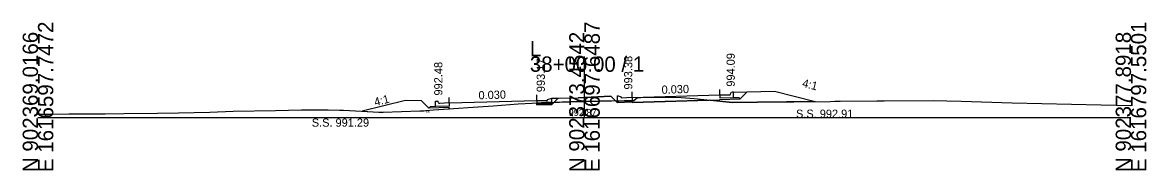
# Model space of a CAD drawing. Extents: x 1009 to 7438, y -1586 to 7964.
# Drawn here: x 3032.1 to 3237.7, y 5914 to 5941 of the extents above; entities that cross this region are included whole.
import ezdxf

# ---------------------------------------------------------------- set-up
doc = ezdxf.new("R2010")
doc.units = 0
for name, color, linetype in [('Exist Cross Section Cell', 7, 'Continuous'), ('Exist XS Center Line Elevation Label', 7, 'Continuous'), ('Exist XS Ground Line', 7, 'Continuous'), ('Prop XS Dump Level', 7, 'Continuous'), ('Prop XS Earthwork Shape', 7, 'Continuous'), ('Prop XS EOT Tick Mark', 7, 'Continuous'), ('Prop XS Finish Grade', 7, 'Continuous'), ('Prop XS Finish Grade CurbGutter', 7, 'Continuous'), ('Prop XS Finish Grade Earthwork', 7, 'Continuous'), ('Prop XS Finish Grade Pavement', 7, 'Continuous'), ('Prop XS Hydro Elevations', 7, 'Continuous'), ('Prop XS Pvmt Edge Slope', 7, 'Continuous'), ('Prop XS SE Text', 7, 'Continuous'), ('Prop XS Side Slope Text', 7, 'Continuous'), ('Prop XS SS Elevation Text', 7, 'Continuous'), ('Prop XS Subgrade CurbGutter', 7, 'Continuous'), ('Prop XS Subgrade Earthwork', 7, 'Continuous')]:
    doc.layers.add(name, color=color, linetype=linetype)

msp = doc.modelspace()

# ---------------------------------------------------------------- linework, layer by layer
at = {"layer": 'Exist Cross Section Cell'}
for p, q in [((3134.89, 5923.73), (3134.89, 5934.84)), ((3034.89, 5923.73), (3134.89, 5923.73)), ((3134.89, 5923.73), (3234.89, 5923.73))]:
    msp.add_line(p, q, dxfattribs=at)
at = {"layer": 'Exist XS Ground Line'}
for p, q in [((3107.24, 5925.08), (3118.2, 5925.81)), ((3118.2, 5925.81), (3122.77, 5926.19)), ((3122.77, 5926.19), (3127.86, 5926.41)), ((3127.86, 5926.41), (3128.42, 5926.43)), ((3128.42, 5926.43), (3132.18, 5926.53)), ((3132.18, 5926.53), (3134.89, 5926.6)), ((3134.89, 5926.6), (3142.32, 5926.79)), ((3142.32, 5926.79), (3143.94, 5926.8)), ((3143.94, 5926.8), (3144.62, 5927.33)), ((3144.62, 5927.33), (3145.2, 5927.34)), ((3145.2, 5927.34), (3149.54, 5927.43)), ((3149.54, 5927.43), (3150.62, 5927.41)), ((3150.62, 5927.41), (3152.55, 5927.35)), ((3152.55, 5927.35), (3154.93, 5927.15)), ((3154.93, 5927.15), (3161.98, 5926.45)), ((3161.98, 5926.45), (3166.57, 5926.5)), ((3166.57, 5926.5), (3179.84, 5926.64)), ((3179.84, 5926.64), (3180.7, 5926.66)), ((3180.7, 5926.66), (3181.66, 5926.67)), ((3181.66, 5926.67), (3188.36, 5926.72)), ((3188.36, 5926.72), (3189.7, 5926.73)), ((3189.7, 5926.73), (3198.69, 5926.8)), ((3198.69, 5926.8), (3201.22, 5926.73)), ((3201.22, 5926.73), (3203.8, 5926.69)), ((3203.8, 5926.69), (3213.15, 5926.35)), ((3213.15, 5926.35), (3234.89, 5925.92)), ((3034.89, 5924.28), (3037.6, 5924.32)), ((3037.6, 5924.32), (3040.56, 5924.36)), ((3040.56, 5924.36), (3047.18, 5924.39)), ((3047.18, 5924.39), (3050.57, 5924.42)), ((3050.57, 5924.42), (3056.77, 5924.49)), ((3056.77, 5924.49), (3060.58, 5924.54)), ((3060.58, 5924.54), (3066.35, 5924.69)), ((3066.35, 5924.69), (3070.59, 5924.83)), ((3070.59, 5924.83), (3078.34, 5924.99)), ((3078.34, 5924.99), (3083.1, 5925.11)), ((3083.1, 5925.11), (3084.85, 5925.1)), ((3084.85, 5925.1), (3087.99, 5925.08)), ((3087.99, 5925.08), (3090.09, 5925.03)), ((3090.09, 5925.03), (3090.79, 5925.01)), ((3090.79, 5925.01), (3092.99, 5924.91)), ((3092.99, 5924.91), (3097.28, 5924.67)), ((3097.28, 5924.67), (3098.03, 5924.67)), ((3098.03, 5924.67), (3104.79, 5924.91)), ((3104.79, 5924.91), (3105.52, 5924.93)), ((3105.52, 5924.93), (3105.87, 5924.95)), ((3105.87, 5924.95), (3107.24, 5925.08))]:
    msp.add_line(p, q, dxfattribs=at)
at = {"layer": 'Prop XS Dump Level'}
for p, q in [((3143.64, 5927.36), (3159.64, 5927.84)), ((3143.64, 5927.36), (3159.64, 5927.84)), ((3110.14, 5926.35), (3126.14, 5926.83)), ((3110.14, 5926.35), (3126.14, 5926.83))]:
    msp.add_line(p, q, dxfattribs=at)
at = {"layer": 'Prop XS Earthwork Shape'}
for points in [[(3163.39, 5927.12), (3164.64, 5928.37), (3169.64, 5928.48), (3177.1, 5926.61), (3166.57, 5926.5), (3161.98, 5926.45), (3157.78, 5926.87), (3159.64, 5926.92), (3159.64, 5927.01)], [(3105.87, 5924.95), (3107.24, 5925.08), (3110.14, 5925.27), (3110.14, 5925.44), (3110.14, 5925.52), (3106.39, 5925.41), (3105.04, 5926.77), (3102.14, 5926.83), (3094.2, 5924.84), (3097.28, 5924.67), (3098.03, 5924.67), (3104.79, 5924.91), (3105.52, 5924.93)], [(3128.67, 5926.3), (3128.89, 5926.31), (3128.89, 5926.44), (3128.42, 5926.43), (3127.86, 5926.41), (3126.14, 5926.34), (3126.14, 5926.25), (3127.64, 5926.3), (3128.64, 5926.33)], [(3126.14, 5926.25), (3127.64, 5926.3), (3128.64, 5926.33), (3128.67, 5926.3), (3128.89, 5926.09), (3126.14, 5926)], [(3128.67, 5926.3), (3128.89, 5926.31), (3128.89, 5926.44), (3129.26, 5926.45), (3128.89, 5926.09)], [(3130.07, 5927.24), (3130.12, 5927.24), (3133.76, 5927.31), (3139.74, 5927.59), (3140.59, 5926.74), (3134.89, 5926.6), (3132.18, 5926.53), (3129.26, 5926.45)], [(3141.14, 5926.7), (3140.88, 5926.45), (3140.59, 5926.74), (3140.9, 5926.75), (3140.9, 5926.7)], [(3142.14, 5926.73), (3141.14, 5926.7), (3140.88, 5926.45), (3143.64, 5926.53), (3143.64, 5926.78)], [(3142.14, 5926.73), (3141.14, 5926.7), (3140.9, 5926.7), (3140.9, 5926.75), (3142.32, 5926.79), (3143.64, 5926.8), (3143.64, 5926.78)], [(3149.54, 5927.43), (3150.62, 5927.41), (3152.55, 5927.35), (3154.93, 5927.15), (3157.78, 5926.87), (3143.64, 5926.44), (3143.64, 5926.53), (3143.64, 5926.78), (3143.64, 5926.8), (3143.94, 5926.8), (3144.62, 5927.33), (3145.2, 5927.34)]]:
    msp.add_lwpolyline(points, close=True, dxfattribs=at)
at = {"layer": 'Prop XS EOT Tick Mark'}
for p, q in [((3126.14, 5926.83), (3126.14, 5927.83)), ((3143.64, 5927.36), (3143.64, 5928.36)), ((3159.64, 5927.84), (3159.64, 5928.84)), ((3110.14, 5926.35), (3110.14, 5927.35))]:
    msp.add_line(p, q, dxfattribs=at)
at = {"layer": 'Prop XS Finish Grade'}
for p, q in [((3162.14, 5928.32), (3164.64, 5928.37)), ((3128.89, 5927.21), (3130.12, 5927.24))]:
    msp.add_line(p, q, dxfattribs=at)
at = {"layer": 'Prop XS Finish Grade CurbGutter'}
for p, q in [((3159.64, 5927.84), (3161.39, 5927.82)), ((3161.39, 5927.82), (3161.52, 5927.84)), ((3161.52, 5927.84), (3161.61, 5927.94)), ((3161.61, 5927.94), (3161.68, 5928.19)), ((3161.68, 5928.19), (3161.77, 5928.28)), ((3161.89, 5928.32), (3161.77, 5928.28)), ((3162.14, 5928.32), (3161.89, 5928.32)), ((3107.64, 5926.71), (3107.89, 5926.71)), ((3107.89, 5926.71), (3108.02, 5926.69)), ((3108.11, 5926.6), (3108.02, 5926.69)), ((3108.18, 5926.35), (3108.11, 5926.6)), ((3108.27, 5926.25), (3108.18, 5926.35)), ((3108.39, 5926.23), (3108.27, 5926.25)), ((3110.14, 5926.35), (3108.39, 5926.23)), ((3126.14, 5926.83), (3128.14, 5926.79)), ((3128.14, 5926.96), (3128.89, 5927.21)), ((3128.14, 5926.79), (3128.14, 5926.96)), ((3141.65, 5927.39), (3140.9, 5927.64)), ((3141.65, 5927.22), (3141.65, 5927.39)), ((3143.64, 5927.36), (3141.65, 5927.22)), ((3143.64, 5927.36), (3142.89, 5927.31))]:
    msp.add_line(p, q, dxfattribs=at)
at = {"layer": 'Prop XS Finish Grade Earthwork'}
for p, q in [((3164.64, 5928.37), (3169.64, 5928.48)), ((3169.64, 5928.48), (3177.1, 5926.61)), ((3102.14, 5926.83), (3094.2, 5924.84)), ((3105.04, 5926.77), (3102.14, 5926.83)), ((3130.12, 5927.24), (3133.76, 5927.31)), ((3139.74, 5927.59), (3133.76, 5927.31))]:
    msp.add_line(p, q, dxfattribs=at)
at = {"layer": 'Prop XS Finish Grade Pavement'}
for p, q in [((3143.64, 5927.36), (3159.64, 5927.84)), ((3110.14, 5926.35), (3126.14, 5926.83))]:
    msp.add_line(p, q, dxfattribs=at)
at = {"layer": 'Prop XS Pvmt Edge Slope'}
for p, q in [((3107.64, 5925.7), (3106.64, 5925.67)), ((3127.64, 5926.3), (3128.64, 5926.33)), ((3128.64, 5926.33), (3128.89, 5926.09)), ((3128.67, 5926.3), (3128.89, 5926.31)), ((3141.14, 5926.7), (3140.88, 5926.45)), ((3142.14, 5926.73), (3140.9, 5926.7)), ((3162.14, 5927.33), (3163.14, 5927.36)), ((3163.14, 5927.36), (3163.39, 5927.12)), ((3106.64, 5925.67), (3106.39, 5925.41))]:
    msp.add_line(p, q, dxfattribs=at)
at = {"layer": 'Prop XS Subgrade CurbGutter'}
for p, q in [((3159.64, 5927.84), (3159.64, 5927.26)), ((3162.14, 5927.33), (3162.14, 5928.32)), ((3107.64, 5925.7), (3107.64, 5926.71)), ((3110.14, 5925.77), (3107.64, 5925.7)), ((3110.14, 5926.35), (3110.14, 5925.77)), ((3126.14, 5926.83), (3126.14, 5926.25)), ((3126.14, 5926.25), (3127.64, 5926.3)), ((3128.89, 5926.31), (3128.89, 5927.21)), ((3140.9, 5926.7), (3140.9, 5927.64)), ((3143.64, 5926.78), (3142.14, 5926.73)), ((3143.64, 5927.36), (3143.64, 5926.78)), ((3159.64, 5927.26), (3162.14, 5927.33))]:
    msp.add_line(p, q, dxfattribs=at)
at = {"layer": 'Prop XS Subgrade Earthwork'}
for p, q in [((3163.39, 5927.12), (3164.64, 5928.37)), ((3106.39, 5925.41), (3105.04, 5926.77)), ((3126.14, 5926), (3126.14, 5926.34)), ((3126.14, 5926), (3128.89, 5926.09)), ((3128.89, 5926.09), (3130.07, 5927.24)), ((3140.88, 5926.45), (3139.74, 5927.59)), ((3143.64, 5926.53), (3140.88, 5926.45)), ((3143.64, 5926.44), (3159.64, 5926.92)), ((3143.64, 5926.44), (3143.64, 5926.8)), ((3143.64, 5926.44), (3143.64, 5926.8)), ((3143.64, 5926.44), (3143.64, 5926.53)), ((3159.64, 5927.01), (3163.39, 5927.12)), ((3159.64, 5926.92), (3159.64, 5927.01)), ((3110.14, 5925.52), (3106.39, 5925.41)), ((3110.14, 5925.44), (3110.14, 5925.52)), ((3110.14, 5925.44), (3110.14, 5925.27))]:
    msp.add_line(p, q, dxfattribs=at)

# ---------------------------------------------------------------- texts
at = {"layer": 'Exist Cross Section Cell'}
for s, p in [('E 1616597.7472', (3037.69, 5913.73)), ('E 1616697.6487', (3137.69, 5913.73)), ('E 1616797.5501', (3237.69, 5913.73)), ('N 902369.0166', (3034.89, 5913.73)), ('N 902373.4542', (3134.89, 5913.73)), ('N 902377.8918', (3234.89, 5913.73))]:
    msp.add_text(s, height=2.8, rotation=90, dxfattribs=at).set_placement(p)
for s, p in [('L', (3124.89, 5934.84)), ('38+00.00 / 1', (3124.89, 5932.04))]:
    msp.add_text(s, height=2.8, dxfattribs=at).set_placement(p)
at = {"layer": 'Exist XS Center Line Elevation Label'}
msp.add_text('992.87', height=1.25, dxfattribs=at).set_placement((3131.99, 5923.97))
at = {"layer": 'Prop XS Dump Level'}
for p in [(3142.33, 5926.49), (3142.33, 5926.49), (3142.33, 5926.49), (3105.87, 5924.65)]:
    msp.add_text('Eop', height=0.3, dxfattribs=at).set_placement(p)
at = {"layer": 'Prop XS Hydro Elevations'}
for s, p in [('993.17', (3127.64, 5928.33)), ('993.38', (3143.64, 5928.81)), ('994.09', (3162.39, 5929.32)), ('992.48', (3108.89, 5927.71))]:
    msp.add_text(s, height=1.5, rotation=90, dxfattribs=at).set_placement(p)
at = {"layer": 'Prop XS SE Text'}
for p in [(3115.52, 5927.01), (3149.02, 5928.02)]:
    msp.add_text('0.030', height=1.5, rotation=1.7184, dxfattribs=at).set_placement(p)
at = {"layer": 'Prop XS Side Slope Text'}
for rotation, p in [(345.9638, (3174.62, 5929.32)), (14.0362, (3096.6, 5925.76))]:
    msp.add_text('4:1', height=1.5, rotation=rotation, dxfattribs=at).set_placement(p)
at = {"layer": 'Prop XS SS Elevation Text'}
for s, p in [('S.S. 992.91', (3173.6, 5923.64)), ('S.S. 991.29', (3084.99, 5922.02))]:
    msp.add_text(s, height=1.5, dxfattribs=at).set_placement(p)

doc.saveas('drawing.dxf')
